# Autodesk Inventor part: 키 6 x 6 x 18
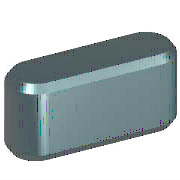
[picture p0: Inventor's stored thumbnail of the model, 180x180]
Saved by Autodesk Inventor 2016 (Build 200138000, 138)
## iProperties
Created: 2012-02
Part Number: 키 6 x 6 x 18
Material: 강철, 연강
Description: 키 및 해당 키홈
Document SubType Name: Modeling
Standard: KS B 1311
Designer: mduedu
Standards Organization: KS
Language: ko-KR
Size Designation: 6 x 6 x 18
Categories: <MemberInstance><Categories><Category DisplayName="샤프트 부품" InternalName="7f7aeb1f-a693-4053-b835-cee3144e0d98" Mnemonic="SHFT"><Category DisplayName="키" Interna
Density: 1 g/cm^3
Appearance: 노란색
IsCustomPart: 1
Author: mduedu
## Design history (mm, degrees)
workplane "Work Plane1"
workplane "Work Plane2"
sketch "스케치1"
  geometry: L1 (3, 3)-(15, 3); L2 (15, -3)-(3, -3); L3 (0, 9.4)-(0, -7.4) reference; L4 (-5, 0)-(30, 0) reference; L5 (18, 0)-(18, 7); A1 r 3 centre (3, 0) between (3, 3) and (3, -3); A2 r 3 centre (15, 0) between (15, -3) and (15, 3)
  constraints: 6 end point, 5 point on circle, 4 tangent, 3 point on line, 2 centre point, 1 horizontal, 1 parallel, 1 perpendicular
  dimensions: "d0" = 3 radius of A1 (= 0.5 x PB); "d13" = 3 radius of A2 (= 0.5 x PB); "d14" = 18 distance between parallel lines of L5 L3 (= NLG)
extrude "본체1" new body sketch "스케치1" taper "d3" = 0 deg; stored distance "d4" = 10
workplane "Work Plane3"
body "Solid1"
chamfer "모따기1" distance "d8" = 0.4 (= PHH); stored, may be unused: second distance "d9" = 0.4 (= PHH), angle "d15" = 45 deg
other parameters: "d1" = -3.5 (= -PNT), "d2" = 2.5 (= PH - PNT), "NLG" = 18 [user parameter; used in 3 equation terms], "PB" = 6 [user parameter; used in 2 equation terms], "PNT" = 3.5 [user parameter; used in 2 equation terms], "PH" = 6 [user parameter; used in 1 equation term], "PHH" = 0.4 [user parameter; used in 2 equation terms], "d10" = 0, "d16" = 0, "d17" = 0, "d18" = 0, "WDMIN" = 17 [user parameter], "PLB2" = 18 (= NLG) [user parameter], "WDMAX" = 22 [user parameter], "PLB1" = 18 (= NLG) [user parameter], "RR" = 0.16 [user parameter], "PUEB" = 2.8 [user parameter]
